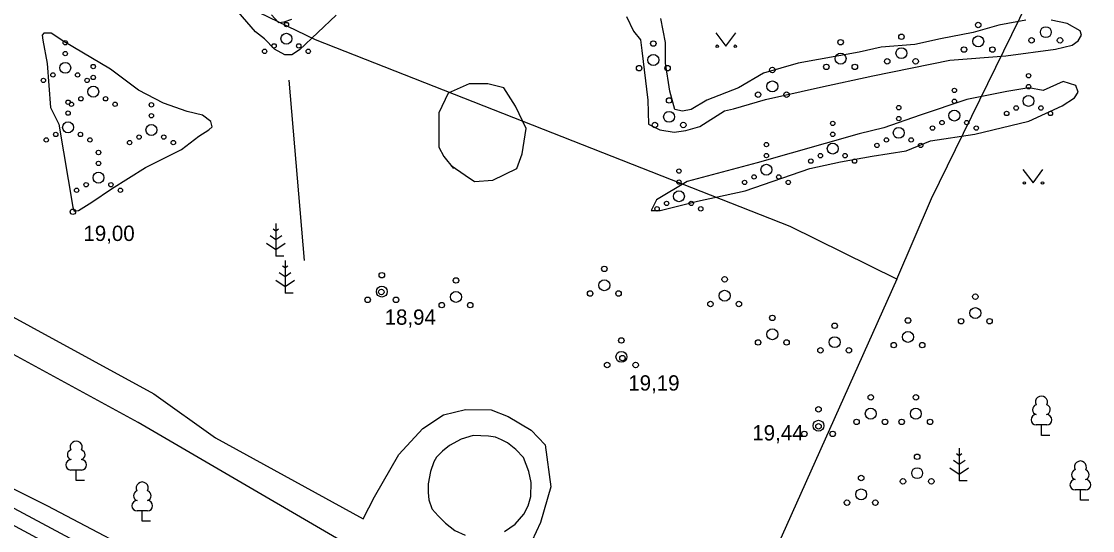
# Model space of a CAD drawing. Extents: x 713497 to 713863, y 6590062 to 6590327.
# Drawn here: x 713754.44 to 713803.4, y 6590187.1 to 6590210.37 of the extents above; entities that cross this region are included whole.
import ezdxf

# ---------------------------------------------------------------- set-up
doc = ezdxf.new("R2010")
doc.units = 0
for name, color, linetype in [('AED', 7, 'Continuous'), ('HALJASTUS', 7, 'Continuous'), ('KORGUS', 7, 'Continuous'), ('KPKAABEL', 7, 'Continuous'), ('MPKAABEL', 7, 'Continuous'), ('PUU', 7, 'Continuous'), ('TEE', 7, 'Continuous')]:
    doc.layers.add(name, color=color, linetype=linetype)

msp = doc.modelspace()

# ---------------------------------------------------------------- linework, layer by layer
at = {"layer": 'AED'}
msp.add_lwpolyline([(713842.75, 6590140.44), (713835.11, 6590144.59), (713824.81, 6590150.12), (713803.9, 6590161.43), (713731.96, 6590199.96)], dxfattribs=at)
at = {"layer": 'HALJASTUS'}
for p, q in [((713786.177, 6590209.847), (713786.64, 6590209.24)), ((713786.64, 6590209.24), (713787.086, 6590209.847)), ((713800.217, 6590203.597), (713800.68, 6590202.99)), ((713800.68, 6590202.99), (713801.126, 6590203.597))]:
    msp.add_line(p, q, dxfattribs=at)
for points in [[(713768.82, 6590210.66), (713767.15, 6590209.08), (713766.8, 6590208.84), (713766.48, 6590208.84), (713766.01, 6590209.11), (713765.54, 6590209.57), (713765.13, 6590209.9), (713764.14, 6590211.04)], [(713765.87, 6590210.68), (713766.19, 6590210.33), (713766.45, 6590210.36), (713766.8, 6590210.48)], [(713782.1, 6590210.59), (713782.42, 6590209.93), (713782.73, 6590209.53), (713782.79, 6590209.04), (713783.07, 6590206.77), (713783.1, 6590205.68), (713783.61, 6590205.42), (713784.27, 6590205.31), (713784.81, 6590205.39), (713785.44, 6590205.57), (713786.58, 6590206.28), (713786.98, 6590206.37), (713788.44, 6590206.8), (713790.96, 6590207.37), (713793.36, 6590207.88), (713796.88, 6590208.6), (713799.43, 6590208.8), (713801.71, 6590209.11), (713802.46, 6590209.28), (713802.74, 6590209.48), (713802.89, 6590209.74), (713802.83, 6590209.94), (713802.23, 6590210.28), (713801.51, 6590210.43)], [(713792.73, 6590208.97), (713789.94, 6590208.47), (713788.36, 6590208.01), (713787.22, 6590207.33), (713785.76, 6590206.78), (713785.05, 6590206.35), (713784.65, 6590206.27), (713784.3, 6590206.35), (713784.07, 6590207.18), (713783.87, 6590208.47), (713783.87, 6590209.41), (713783.67, 6590210.5)], [(713800.34, 6590210.43), (713799.11, 6590210.2), (713797.94, 6590209.86), (713796.45, 6590209.57), (713795.28, 6590209.31), (713793.73, 6590209.2), (713792.73, 6590208.97)], [(713755.41, 6590209.51), (713755.61, 6590208.45), (713755.76, 6590206.44), (713756.14, 6590205.68), (713756.78, 6590201.88), (713756.84, 6590201.7), (713757.04, 6590201.73), (713757.66, 6590202.11), (713758.56, 6590202.72), (713760.11, 6590203.69), (713761.75, 6590204.51), (713762.54, 6590205.12), (713763.01, 6590205.41), (713763.16, 6590205.56), (713763.1, 6590205.79), (713762.72, 6590206.09), (713762.02, 6590206.26), (713760.93, 6590206.64), (713759.79, 6590207.23), (713758.51, 6590208.19), (713756.37, 6590209.45), (713755.79, 6590209.83), (713755.46, 6590209.83), (713755.38, 6590209.74), (713755.41, 6590209.51)], [(713767.37, 6590199.45), (713766.67, 6590207.69)], [(713774.08, 6590203.78), (713774.72, 6590203.35), (713775.15, 6590203.05), (713775.99, 6590203.11), (713777.08, 6590203.65), (713777.32, 6590204.32), (713777.51, 6590205.47), (713777.02, 6590206.5), (713776.48, 6590207.34), (713775.75, 6590207.52), (713774.9, 6590207.52), (713773.94, 6590207.1), (713773.51, 6590206.19), (713773.51, 6590205.29), (713773.51, 6590204.62), (713773.75, 6590204.2), (713774.18, 6590203.65)], [(713787.52, 6590202.63), (713790.47, 6590203.65), (713791.87, 6590203.96), (713793.33, 6590204.22), (713794.88, 6590204.45), (713795.99, 6590204.91), (713798.02, 6590205.22), (713800.48, 6590205.82), (713802, 6590206.51), (713802.57, 6590206.88), (713802.74, 6590207.14), (713802.63, 6590207.45), (713802.06, 6590207.63), (713801.14, 6590207.22), (713800.48, 6590207.34), (713799.48, 6590207.17), (713797.65, 6590206.8), (713795.51, 6590206.08), (713793.85, 6590205.51), (713792.73, 6590205.24), (713788.06, 6590203.91), (713784.86, 6590203.06), (713783.46, 6590202.21), (713783.22, 6590201.73), (713783.64, 6590201.73), (713785.34, 6590202.15), (713787.52, 6590202.63)], [(713841.26, 6590142.2), (713834.39, 6590145.82), (713823.52, 6590151.93), (713808.23, 6590160.2), (713806.22, 6590161.53), (713798.4, 6590165.35), (713781.9, 6590174.22), (713774.18, 6590178.32), (713771.41, 6590180.04), (713767.95, 6590181.54), (713761.08, 6590185.35), (713755.64, 6590188.21), (713751.36, 6590190.34), (713748.73, 6590191.96), (713741.58, 6590196.11), (713734, 6590200.4)], [(713732.19, 6590199.21), (713738.7, 6590195.69), (713747.61, 6590190.82), (713767.02, 6590180.35), (713771.65, 6590178.11), (713786.98, 6590169.69), (713793.79, 6590166.16), (713813.16, 6590155.69), (713817.55, 6590153.26), (713832.96, 6590144.79), (713835.16, 6590143.78), (713841.97, 6590140.16)]]:
    msp.add_lwpolyline(points, dxfattribs=at)
for centre, radius in [((713766.55, 6590210.23), 0.1), ((713798.17, 6590210.21), 0.125), ((713801.26, 6590209.88), 0.25), ((713766.55, 6590209.58), 0.25), ((713794.66, 6590209.67), 0.125), ((713798.17, 6590209.46), 0.25), ((713800.61, 6590209.505), 0.125), ((713801.91, 6590209.505), 0.125), ((713756.44, 6590209.4), 0.1), ((713765.985, 6590209.255), 0.1), ((713767.115, 6590209.255), 0.1), ((713783.32, 6590209.36), 0.125), ((713786.239, 6590209.24), 0.055), ((713787.068, 6590209.24), 0.055), ((713791.88, 6590209.42), 0.125), ((713794.66, 6590208.92), 0.25), ((713797.52, 6590209.085), 0.125), ((713798.82, 6590209.085), 0.125), ((713756.44, 6590208.9), 0.1), ((713765.55, 6590209.005), 0.1), ((713767.55, 6590209.005), 0.1), ((713783.32, 6590208.61), 0.25), ((713791.88, 6590208.67), 0.25), ((713794.01, 6590208.545), 0.125), ((713795.31, 6590208.545), 0.125), ((713756.44, 6590208.25), 0.25), ((713757.72, 6590208.31), 0.1), ((713782.67, 6590208.235), 0.125), ((713783.97, 6590208.235), 0.125), ((713788.76, 6590208.15), 0.125), ((713791.23, 6590208.295), 0.125), ((713792.53, 6590208.295), 0.125), ((713755.44, 6590207.675), 0.1), ((713755.875, 6590207.925), 0.1), ((713757.005, 6590207.925), 0.1), ((713757.44, 6590207.675), 0.1), ((713757.72, 6590207.81), 0.1), ((713788.76, 6590207.4), 0.25), ((713800.47, 6590207.89), 0.1), ((713757.72, 6590207.16), 0.25), ((713797.08, 6590207.22), 0.1), ((713800.47, 6590207.39), 0.1), ((713756.57, 6590206.68), 0.1), ((713756.72, 6590206.585), 0.1), ((713757.155, 6590206.835), 0.1), ((713758.285, 6590206.835), 0.1), ((713758.72, 6590206.585), 0.1), ((713784.04, 6590206.76), 0.125), ((713788.11, 6590207.025), 0.125), ((713789.41, 6590207.025), 0.125), ((713797.08, 6590206.72), 0.1), ((713800.47, 6590206.74), 0.25), ((713756.57, 6590206.18), 0.1), ((713760.38, 6590206.56), 0.1), ((713784.04, 6590206.01), 0.25), ((713794.54, 6590206.43), 0.1), ((713797.08, 6590206.07), 0.25), ((713799.47, 6590206.165), 0.1), ((713799.905, 6590206.415), 0.1), ((713801.035, 6590206.415), 0.1), ((713801.47, 6590206.165), 0.1), ((713756.57, 6590205.53), 0.25), ((713760.38, 6590206.06), 0.1), ((713783.39, 6590205.635), 0.125), ((713784.69, 6590205.635), 0.125), ((713791.52, 6590205.71), 0.1), ((713794.54, 6590205.93), 0.1), ((713796.515, 6590205.745), 0.1), ((713797.645, 6590205.745), 0.1), ((713756.005, 6590205.205), 0.1), ((713757.135, 6590205.205), 0.1), ((713760.38, 6590205.41), 0.25), ((713791.52, 6590205.21), 0.1), ((713794.54, 6590205.28), 0.25), ((713796.08, 6590205.495), 0.1), ((713798.08, 6590205.495), 0.1), ((713755.57, 6590204.955), 0.1), ((713757.57, 6590204.955), 0.1), ((713759.38, 6590204.835), 0.1), ((713759.815, 6590205.085), 0.1), ((713760.945, 6590205.085), 0.1), ((713761.38, 6590204.835), 0.1), ((713788.49, 6590204.74), 0.1), ((713791.52, 6590204.56), 0.25), ((713793.54, 6590204.705), 0.1), ((713793.975, 6590204.955), 0.1), ((713795.105, 6590204.955), 0.1), ((713795.54, 6590204.705), 0.1), ((713757.96, 6590204.38), 0.1), ((713788.49, 6590204.24), 0.1), ((713790.955, 6590204.235), 0.1), ((713792.085, 6590204.235), 0.1), ((713757.96, 6590203.88), 0.1), ((713788.49, 6590203.59), 0.25), ((713790.52, 6590203.985), 0.1), ((713792.52, 6590203.985), 0.1), ((713757.96, 6590203.23), 0.25), ((713784.49, 6590203.53), 0.1), ((713787.925, 6590203.265), 0.1), ((713789.055, 6590203.265), 0.1), ((713756.96, 6590202.655), 0.1), ((713757.395, 6590202.905), 0.1), ((713758.525, 6590202.905), 0.1), ((713758.96, 6590202.655), 0.1), ((713784.49, 6590203.03), 0.1), ((713787.49, 6590203.015), 0.1), ((713789.49, 6590203.015), 0.1), ((713800.279, 6590202.99), 0.055), ((713801.108, 6590202.99), 0.055), ((713784.49, 6590202.38), 0.25), ((713783.49, 6590201.805), 0.1), ((713783.925, 6590202.055), 0.1), ((713785.055, 6590202.055), 0.1), ((713785.49, 6590201.805), 0.1), ((713770.91, 6590198.77), 0.125), ((713781.08, 6590199.06), 0.125), ((713774.3, 6590198.53), 0.125), ((713781.08, 6590198.31), 0.25), ((713786.58, 6590198.58), 0.125), ((713770.91, 6590198.02), 0.25), ((713774.3, 6590197.78), 0.25), ((713780.43, 6590197.935), 0.125), ((713781.73, 6590197.935), 0.125), ((713786.58, 6590197.83), 0.25), ((713798.04, 6590197.79), 0.125), ((713770.26, 6590197.645), 0.125), ((713771.56, 6590197.645), 0.125), ((713773.65, 6590197.405), 0.125), ((713774.95, 6590197.405), 0.125), ((713785.93, 6590197.455), 0.125), ((713787.23, 6590197.455), 0.125), ((713788.76, 6590196.82), 0.125), ((713798.04, 6590197.04), 0.25), ((713791.61, 6590196.46), 0.125), ((713794.96, 6590196.7), 0.125), ((713797.39, 6590196.665), 0.125), ((713798.69, 6590196.665), 0.125), ((713781.86, 6590195.79), 0.125), ((713788.76, 6590196.07), 0.25), ((713791.61, 6590195.71), 0.25), ((713794.96, 6590195.95), 0.25), ((713788.11, 6590195.695), 0.125), ((713789.41, 6590195.695), 0.125), ((713790.96, 6590195.335), 0.125), ((713792.26, 6590195.335), 0.125), ((713794.31, 6590195.575), 0.125), ((713795.61, 6590195.575), 0.125), ((713781.86, 6590195.04), 0.25), ((713781.21, 6590194.665), 0.125), ((713782.51, 6590194.665), 0.125), ((713793.26, 6590193.19), 0.125), ((713795.32, 6590193.19), 0.125), ((713790.87, 6590192.64), 0.125), ((713793.26, 6590192.44), 0.25), ((713795.32, 6590192.44), 0.25), ((713790.87, 6590191.89), 0.25), ((713792.61, 6590192.065), 0.125), ((713793.91, 6590192.065), 0.125), ((713794.67, 6590192.065), 0.125), ((713795.97, 6590192.065), 0.125), ((713790.22, 6590191.515), 0.125), ((713791.52, 6590191.515), 0.125), ((713795.38, 6590190.47), 0.125), ((713792.82, 6590189.5), 0.125), ((713795.38, 6590189.72), 0.25), ((713794.73, 6590189.345), 0.125), ((713796.03, 6590189.345), 0.125), ((713792.82, 6590188.75), 0.25), ((713792.17, 6590188.375), 0.125), ((713793.47, 6590188.375), 0.125)]:
    msp.add_circle(centre, radius, dxfattribs=at)
at = {"layer": 'KORGUS'}
for centre in [(713756.79, 6590201.67), (713770.89, 6590198), (713781.91, 6590194.98), (713790.87, 6590191.86)]:
    msp.add_circle(centre, 0.125, dxfattribs=at)
at = {"layer": 'KPKAABEL'}
for points in [[(713794.45, 6590198.59), (713796.04, 6590202.27), (713815.88, 6590242.79)], [(713794.45, 6590198.59), (713786.13, 6590180.02), (713781.379, 6590168.923), (713780.962, 6590168.239), (713779.091, 6590164.176), (713775.448, 6590156.503), (713774.002, 6590151.688), (713770.408, 6590144.999), (713769.646, 6590143.487), (713765.21, 6590132.86), (713761.14, 6590113.48)]]:
    msp.add_lwpolyline(points, dxfattribs=at)
at = {"layer": 'MPKAABEL'}
msp.add_lwpolyline([(713794.45, 6590198.59), (713789.58, 6590201), (713767.873, 6590209.538), (713741.326, 6590222.344), (713733.59, 6590226.08)], dxfattribs=at)
at = {"layer": 'PUU'}
for p, q in [((713766.07, 6590200.79), (713765.946, 6590200.873)), ((713766.07, 6590201.14), (713766.07, 6590199.64)), ((713766.194, 6590200.873), (713766.07, 6590200.79)), ((713766.07, 6590200.39), (713765.803, 6590200.568)), ((713766.337, 6590200.568), (713766.07, 6590200.39)), ((713765.646, 6590200.229), (713766.07, 6590199.947)), ((713766.07, 6590199.947), (713766.494, 6590200.229)), ((713766.43, 6590199.64), (713766.07, 6590199.64)), ((713766.49, 6590199.45), (713766.49, 6590197.95)), ((713766.49, 6590198.7), (713766.223, 6590198.878)), ((713766.49, 6590199.1), (713766.366, 6590199.183)), ((713766.614, 6590199.183), (713766.49, 6590199.1)), ((713766.757, 6590198.878), (713766.49, 6590198.7)), ((713766.066, 6590198.539), (713766.49, 6590198.257)), ((713766.49, 6590198.257), (713766.914, 6590198.539)), ((713766.85, 6590197.95), (713766.49, 6590197.95)), ((713801.3, 6590191.925), (713800.82, 6590191.925)), ((713801.06, 6590191.45), (713801.06, 6590191.925)), ((713801.44, 6590191.45), (713801.06, 6590191.45)), ((713797.3, 6590190.52), (713797.176, 6590190.603)), ((713797.3, 6590190.87), (713797.3, 6590189.37)), ((713797.424, 6590190.603), (713797.3, 6590190.52)), ((713797.3, 6590190.12), (713797.033, 6590190.298)), ((713797.567, 6590190.298), (713797.3, 6590190.12)), ((713757.18, 6590189.865), (713756.7, 6590189.865)), ((713756.94, 6590189.39), (713756.94, 6590189.865)), ((713796.876, 6590189.959), (713797.3, 6590189.677)), ((713797.3, 6590189.677), (713797.724, 6590189.959)), ((713757.32, 6590189.39), (713756.94, 6590189.39)), ((713797.66, 6590189.37), (713797.3, 6590189.37)), ((713803.08, 6590188.955), (713802.6, 6590188.955)), ((713802.84, 6590188.48), (713802.84, 6590188.955)), ((713803.22, 6590188.48), (713802.84, 6590188.48)), ((713760.2, 6590187.995), (713759.72, 6590187.995)), ((713759.96, 6590187.52), (713759.96, 6590187.995)), ((713760.34, 6590187.52), (713759.96, 6590187.52))]:
    msp.add_line(p, q, dxfattribs=at)
for centre, radius, start, end in [((713801.06, 6590192.97), 0.277, 332.5799, 207.4201), ((713800.89, 6590192.623), 0.233, 109.0217, 253.1415), ((713801.23, 6590192.623), 0.233, 286.8508, 70.9859), ((713800.823, 6590192.162), 0.238, 90.0016, 269.3953), ((713801.297, 6590192.162), 0.238, 270.6047, 89.9984), ((713756.94, 6590190.91), 0.277, 332.5799, 207.4201), ((713756.77, 6590190.563), 0.233, 109.0217, 253.1415), ((713757.11, 6590190.563), 0.233, 286.8508, 70.9859), ((713756.703, 6590190.102), 0.238, 90.0016, 269.3953), ((713757.177, 6590190.102), 0.238, 270.6047, 89.9984), ((713802.84, 6590190), 0.277, 332.5799, 207.4201), ((713802.67, 6590189.653), 0.233, 109.0217, 253.1415), ((713803.01, 6590189.653), 0.233, 286.8508, 70.9859), ((713759.96, 6590189.04), 0.277, 332.5799, 207.4201), ((713802.603, 6590189.192), 0.238, 90.0016, 269.3953), ((713803.077, 6590189.192), 0.238, 270.6047, 89.9984), ((713759.79, 6590188.693), 0.233, 109.0217, 253.1415), ((713760.13, 6590188.693), 0.233, 286.8508, 70.9859), ((713759.723, 6590188.232), 0.238, 90.0016, 269.3953), ((713760.197, 6590188.232), 0.238, 270.6047, 89.9984)]:
    msp.add_arc(centre, radius, start, end, dxfattribs=at)
at = {"layer": 'TEE'}
for points in [[(713733.569, 6590204.065), (713734.704, 6590204.149), (713735.736, 6590204.225), (713736.62, 6590204.29), (713737.732, 6590204.372), (713740.042, 6590203.476), (713746.531, 6590200.956), (713752.011, 6590197.97), (713760.496, 6590193.349), (713763.3, 6590191.34), (713770.05, 6590187.63), (713770.58, 6590188.64), (713771.69, 6590190.57), (713772.79, 6590191.77), (713773.73, 6590192.39), (713774.74, 6590192.63), (713775.91, 6590192.61), (713776.69, 6590192.31), (713777.74, 6590191.69), (713778.37, 6590191.02), (713778.64, 6590189.09), (713778.16, 6590187.46), (713777.37, 6590185.76)], [(713844.05, 6590146.1), (713839.66, 6590148.3), (713822.24, 6590157.05), (713808.23, 6590164.82), (713794.22, 6590172.59), (713772.5, 6590184.62), (713759.78, 6590192.031), (713751.212, 6590196.696), (713745.898, 6590199.593), (713737.505, 6590202.852), (713737.134, 6590202.824), (713736.264, 6590202.76), (713735.329, 6590202.691), (713734.382, 6590202.621), (713732.876, 6590202.51)], [(713776.51, 6590187.06), (713777, 6590187.39), (713777.4, 6590187.85), (713777.6, 6590188.22), (713777.72, 6590188.65), (713777.74, 6590189.29), (713777.63, 6590189.79), (713777.38, 6590190.43), (713777.03, 6590190.81), (713776.66, 6590191.1), (713776.38, 6590191.25), (713776.1, 6590191.36), (713775.78, 6590191.41), (713775.09, 6590191.44), (713774.53, 6590191.28), (713774, 6590190.98), (713773.68, 6590190.73), (713773.41, 6590190.45), (713773.29, 6590190.24), (713773.13, 6590189.79), (713773.03, 6590189.24), (713773.03, 6590188.84), (713773.06, 6590188.5), (713773.2, 6590188.11), (713773.21, 6590188.08)], [(713773.21, 6590188.08), (713773.49, 6590187.77), (713773.82, 6590187.43), (713774.24, 6590187.1), (713774.72, 6590186.88)]]:
    msp.add_lwpolyline(points, dxfattribs=at)

# ---------------------------------------------------------------- texts
at = {"layer": 'KORGUS'}
for s, p in [('19,00', (713757.271, 6590200.335)), ('18,94', (713771.038, 6590196.505)), ('19,19', (713782.176, 6590193.495)), ('19,44', (713787.843, 6590191.215))]:
    msp.add_text(s, height=0.7, dxfattribs=at).set_placement(p)

doc.saveas('drawing.dxf')
